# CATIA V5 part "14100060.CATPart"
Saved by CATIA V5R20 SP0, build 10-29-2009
Part number: 14100060
Definition: NONE
Nomenclature: 14100060
Source: Unknown
Description: 14100060
Bounding box of the stored display mesh (mm): x -30 to 120, y -64 to 53.915, z -54.1 to 54.1
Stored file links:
  C:\Users\Utente\Desktop\IO LAVORO\3D X SITO CF\X SITO\PLASTICA\RF2\14100060.CATPart
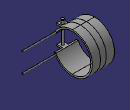
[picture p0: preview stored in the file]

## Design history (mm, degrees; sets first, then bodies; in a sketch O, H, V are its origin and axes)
Body1 "14100060" (main body)
  Solid1: solid without history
